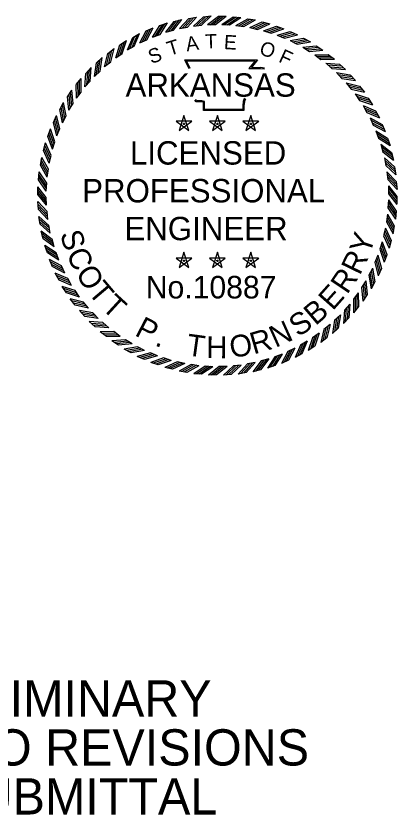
# Model space of a CAD drawing. Extents: x 172 to 3385, y 73 to 2074.
# Drawn here: x 3035 to 3298, y 104 to 655 of the extents above; entities that cross this region are included whole.
import ezdxf

# ---------------------------------------------------------------- set-up
doc = ezdxf.new("R2010")
doc.units = 0
doc.layers.add('G-ANNO-TEXT', color=7, linetype='Continuous')
doc.layers.add('R_Border Prem', color=7, linetype='Continuous')

msp = doc.modelspace()

# ---------------------------------------------------------------- linework, layer by layer
at = {"layer": 'G-ANNO-TEXT'}
for p, q in [((3144.09, 651.46), (3149.34, 652.84)), ((3154.11, 653.5), (3159.46, 654.45)), ((3164.27, 654.72), (3169.68, 655.22)), ((3174.55, 655.02), (3179.98, 655.02)), ((3184.72, 654.61), (3190.13, 654.22)), ((3194.86, 653.3), (3200.22, 652.45)), ((3204.86, 651.15), (3210.14, 649.86)), ((3124.72, 644.92), (3129.67, 647.14)), ((3134.27, 648.59), (3139.39, 650.4)), ((3138.4, 643.99), (3143.66, 645.37)), ((3147.82, 646.53), (3153.18, 647.47)), ((3157.43, 648.29), (3162.84, 648.79)), ((3167.14, 649.25), (3172.58, 649.25)), ((3176.91, 649.4), (3182.33, 649)), ((3186.65, 648.74), (3192.02, 647.9)), ((3196.3, 647.29), (3201.59, 646)), ((3214.65, 648.18), (3219.8, 646.46)), ((3115.51, 640.47), (3120.25, 643.1)), ((3129.21, 640.67), (3134.34, 642.49)), ((3205.8, 645.04), (3210.96, 643.32)), ((3215.09, 642.01), (3220.09, 639.87)), ((3224.17, 644.41), (3229.16, 642.27)), ((3233.33, 639.87), (3238.13, 637.33)), ((3106.69, 635.28), (3111.21, 638.29)), ((3111.82, 631.83), (3116.58, 634.46)), ((3120.33, 636.61), (3125.29, 638.84)), ((3224.09, 638.23), (3228.89, 635.68)), ((3242.1, 634.59), (3246.67, 631.66)), ((3098.33, 629.38), (3102.59, 632.75)), ((3103.73, 626.36), (3108.26, 629.38)), ((3232.74, 633.72), (3237.33, 630.78)), ((3250.39, 628.6), (3254.71, 625.31)), ((3090.49, 622.8), (3094.45, 626.52)), ((3096.12, 620.25), (3100.38, 623.63)), ((3241, 628.5), (3245.32, 625.2)), ((3083.22, 615.61), (3086.86, 619.63)), ((3248.8, 622.63), (3252.83, 618.98)), ((3258.17, 621.95), (3262.19, 618.31)), ((3076.57, 607.83), (3079.86, 612.15)), ((3089.04, 613.52), (3093.01, 617.24)), ((3256.08, 616.13), (3259.8, 612.16)), ((3265.36, 614.68), (3269.08, 610.72)), ((3082.54, 606.24), (3086.19, 610.27)), ((3262.81, 609.05), (3266.19, 604.79)), ((3271.94, 606.84), (3275.31, 602.58)), ((3070.58, 599.54), (3073.51, 604.11)), ((3076.66, 598.44), (3079.97, 602.76)), ((3268.92, 601.44), (3271.94, 596.91)), ((3065.3, 590.77), (3067.84, 595.57)), ((3277.84, 598.48), (3280.85, 593.96)), ((3071.45, 590.18), (3074.39, 594.77)), ((3274.39, 593.35), (3277.02, 588.59)), ((3060.76, 581.61), (3062.89, 586.6)), ((3066.94, 581.53), (3069.48, 586.33)), ((3150.83, 586.54), (3147.44, 576.12)), ((3154.22, 576.13), (3150.84, 586.55)), ((3173.85, 586.54), (3170.46, 576.12)), ((3177.24, 576.13), (3173.86, 586.55)), ((3196.88, 586.54), (3193.48, 576.12)), ((3200.26, 576.13), (3196.88, 586.55)), ((3279.17, 584.84), (3281.4, 579.87)), ((3283.03, 589.66), (3285.66, 584.91)), ((3156.31, 582.56), (3145.35, 582.57)), ((3145.36, 582.56), (3154.22, 576.12)), ((3147.45, 576.13), (3156.32, 582.56)), ((3150.05, 580.81), (3151.68, 580.81)), ((3150.84, 581.4), (3150.84, 580.02)), ((3179.33, 582.56), (3168.37, 582.57)), ((3168.38, 582.56), (3177.24, 576.12)), ((3170.47, 576.13), (3179.34, 582.56)), ((3173.07, 580.81), (3174.7, 580.81)), ((3173.86, 581.4), (3173.86, 580.02)), ((3202.35, 582.56), (3191.39, 582.57)), ((3191.4, 582.56), (3200.26, 576.12)), ((3193.49, 576.13), (3202.36, 582.56)), ((3196.1, 580.81), (3197.72, 580.81)), ((3196.89, 581.4), (3196.89, 580.02)), ((3287.48, 580.45), (3289.7, 575.5)), ((3056.99, 572.09), (3058.71, 577.24)), ((3063.16, 572.53), (3065.3, 577.53)), ((3283.23, 575.96), (3285.05, 570.83)), ((3060.13, 563.24), (3061.85, 568.4)), ((3291.15, 570.9), (3292.96, 565.78)), ((3054.02, 562.3), (3055.31, 567.58)), ((3286.55, 566.77), (3287.93, 561.51)), ((3051.87, 552.3), (3052.72, 557.66)), ((3057.88, 553.74), (3059.17, 559.03)), ((3289.09, 557.35), (3290.03, 551.99)), ((3294.02, 561.08), (3295.4, 555.83)), ((3050.56, 542.16), (3050.95, 547.57)), ((3056.43, 544.09), (3057.27, 549.46)), ((3290.85, 547.74), (3291.35, 542.33)), ((3296.06, 551.06), (3297.01, 545.71)), ((3297.28, 540.9), (3297.78, 535.49)), ((3050.08, 531.94), (3050.03, 537.36)), ((3055.77, 534.35), (3056.17, 539.77)), ((3291.8, 538.03), (3291.86, 532.59)), ((3055.92, 524.58), (3055.87, 530.02)), ((3297.65, 530.67), (3297.7, 525.25)), ((3050.45, 521.71), (3049.95, 527.12)), ((3291.96, 528.26), (3291.56, 522.84)), ((3056.88, 514.87), (3056.38, 520.28)), ((3291.3, 518.52), (3290.46, 513.15)), ((3297.17, 520.45), (3296.77, 515.04)), ((3051.66, 511.55), (3050.72, 516.9)), ((3058.64, 505.26), (3057.69, 510.62)), ((3289.85, 508.87), (3288.56, 503.58)), ((3295.86, 510.31), (3295.01, 504.95)), ((3053.71, 501.53), (3052.33, 506.78)), ((3056.58, 491.71), (3054.77, 496.83)), ((3061.18, 495.84), (3059.8, 501.1)), ((3287.6, 499.37), (3285.88, 494.21)), ((3293.71, 500.3), (3292.42, 495.03)), ((3064.5, 486.65), (3062.68, 491.78)), ((3150.83, 492.15), (3147.44, 481.73)), ((3154.22, 481.74), (3150.84, 492.16)), ((3173.85, 492.15), (3170.46, 481.73)), ((3177.24, 481.74), (3173.86, 492.16)), ((3196.88, 492.15), (3193.48, 481.73)), ((3200.26, 481.74), (3196.88, 492.16)), ((3060.25, 482.16), (3058.03, 487.11)), ((3156.31, 488.17), (3145.35, 488.18)), ((3145.36, 488.17), (3154.22, 481.72)), ((3147.45, 481.74), (3156.32, 488.17)), ((3150.05, 486.42), (3151.68, 486.42)), ((3150.84, 487.01), (3150.84, 485.63)), ((3179.33, 488.17), (3168.37, 488.18)), ((3168.38, 488.17), (3177.24, 481.72)), ((3170.47, 481.74), (3179.34, 488.17)), ((3173.07, 486.42), (3174.7, 486.42)), ((3173.86, 487.01), (3173.86, 485.63)), ((3202.35, 488.17), (3191.39, 488.18)), ((3191.4, 488.17), (3200.26, 481.72)), ((3193.49, 481.74), (3202.36, 488.17)), ((3196.1, 486.42), (3197.72, 486.42)), ((3196.89, 487.01), (3196.89, 485.63)), ((3284.57, 490.08), (3282.43, 485.08)), ((3290.74, 490.51), (3289.02, 485.37)), ((3068.56, 477.77), (3066.33, 482.73)), ((3280.79, 481.08), (3278.24, 476.27)), ((3286.97, 481), (3284.83, 476.01)), ((3064.7, 472.95), (3062.07, 477.69)), ((3073.34, 469.26), (3070.7, 474.02)), ((3276.28, 472.42), (3273.34, 467.84)), ((3282.43, 471.83), (3279.89, 467.04)), ((3069.89, 464.13), (3066.88, 468.65)), ((3078.8, 461.17), (3075.79, 465.7)), ((3271.06, 464.17), (3267.76, 459.84)), ((3075.79, 455.77), (3072.42, 460.03)), ((3084.92, 453.56), (3081.54, 457.82)), ((3277.15, 463.07), (3274.22, 458.5)), ((3265.19, 456.37), (3261.54, 452.33)), ((3271.16, 454.78), (3267.87, 450.46)), ((3082.37, 447.93), (3078.65, 451.89)), ((3091.65, 446.48), (3087.92, 450.45)), ((3258.69, 449.09), (3254.72, 445.36)), ((3264.51, 447), (3260.87, 442.98)), ((3089.56, 440.66), (3085.54, 444.3)), ((3098.93, 439.98), (3094.89, 443.63)), ((3251.61, 442.36), (3247.35, 438.98)), ((3097.34, 434.01), (3093.02, 437.3)), ((3106.73, 434.1), (3102.4, 437.41)), ((3244, 436.24), (3239.47, 433.23)), ((3257.24, 439.81), (3253.28, 436.09)), ((3105.63, 428.02), (3101.06, 430.95)), ((3114.98, 428.89), (3110.4, 431.83)), ((3235.91, 430.78), (3231.15, 428.14)), ((3249.4, 433.23), (3245.14, 429.86)), ((3114.39, 422.74), (3109.6, 425.28)), ((3123.64, 424.38), (3118.83, 426.92)), ((3227.4, 426), (3222.43, 423.77)), ((3241.04, 427.33), (3236.52, 424.32)), ((3123.56, 418.2), (3118.57, 420.33)), ((3132.64, 420.6), (3127.64, 422.74)), ((3141.93, 417.57), (3136.77, 419.29)), ((3218.52, 421.94), (3213.39, 420.12)), ((3232.22, 422.14), (3227.47, 419.51)), ((3133.07, 414.43), (3127.93, 416.15)), ((3151.43, 415.32), (3146.14, 416.61)), ((3161.08, 413.87), (3155.71, 414.71)), ((3170.82, 413.21), (3165.4, 413.61)), ((3190.3, 414.32), (3184.89, 413.82)), ((3199.91, 416.08), (3194.55, 415.13)), ((3209.33, 418.62), (3204.07, 417.24)), ((3213.46, 414.02), (3208.34, 412.21)), ((3223.01, 417.69), (3218.06, 415.47)), ((3142.86, 411.46), (3137.59, 412.75)), ((3152.87, 409.31), (3147.51, 410.16)), ((3163.01, 408), (3157.6, 408.39)), ((3180.59, 413.36), (3175.15, 413.31)), ((3193.62, 409.1), (3188.27, 408.16)), ((3203.64, 411.15), (3198.39, 409.77)), ((3173.23, 407.52), (3167.81, 407.47)), ((3183.46, 407.89), (3178.05, 407.39))]:
    msp.add_line(p, q, dxfattribs=at)
for points in [[(3138.39, 643.98), (3144.08, 651.45)], [(3140.08, 644.41), (3145.78, 651.88)], [(3141.9, 644.93), (3147.59, 652.4)], [(3143.65, 645.37), (3149.34, 652.84)], [(3147.82, 646.52), (3154.11, 653.5)], [(3149.54, 646.81), (3155.83, 653.79)], [(3151.39, 647.18), (3157.68, 654.15)], [(3153.17, 647.48), (3159.46, 654.45)], [(3157.42, 648.28), (3164.26, 654.71)], [(3159.16, 648.43), (3166.01, 654.86)], [(3161.04, 648.64), (3167.88, 655.07)], [(3162.84, 648.79), (3169.68, 655.22)], [(3167.14, 649.24), (3174.54, 655.02)], [(3168.88, 649.22), (3176.29, 655)], [(3170.77, 649.27), (3178.17, 655.04)], [(3172.58, 649.25), (3179.98, 655.02)], [(3176.9, 649.39), (3184.71, 654.61)], [(3178.64, 649.25), (3186.45, 654.46)], [(3180.52, 649.15), (3188.33, 654.37)], [(3182.32, 649), (3190.13, 654.22)], [(3186.64, 648.74), (3194.85, 653.29)], [(3188.36, 648.45), (3196.58, 653)], [(3190.23, 648.2), (3198.45, 652.75)], [(3192.02, 647.9), (3200.23, 652.46)], [(3196.29, 647.28), (3204.86, 651.14)], [(3197.99, 646.85), (3206.55, 650.71)], [(3121.93, 637.31), (3126.31, 645.61)], [(3123.63, 638.12), (3128.02, 646.42)], [(3125.29, 638.84), (3129.67, 647.15)], [(3129.21, 640.67), (3134.26, 648.58)], [(3130.86, 641.23), (3135.92, 649.15)], [(3132.62, 641.9), (3137.68, 649.81)], [(3134.33, 642.49), (3139.39, 650.4)], [(3199.83, 646.45), (3208.39, 650.31)], [(3201.58, 646), (3210.14, 649.86)], [(3205.79, 645.03), (3214.65, 648.17)], [(3207.45, 644.47), (3216.3, 647.61)], [(3209.25, 643.91), (3218.1, 647.05)], [(3210.96, 643.32), (3219.81, 646.46)], [(3111.82, 631.82), (3115.5, 640.46)], [(3113.35, 632.65), (3117.04, 641.29)], [(3114.98, 633.6), (3118.67, 642.24)], [(3116.57, 634.46), (3120.26, 643.1)], [(3120.33, 636.6), (3124.71, 644.91)], [(3215.08, 642.01), (3224.16, 644.41)], [(3216.68, 641.31), (3225.76, 643.71)], [(3218.43, 640.6), (3227.51, 643)], [(3220.08, 639.88), (3229.16, 642.28)], [(3224.08, 638.23), (3233.33, 639.87)], [(3103.73, 626.36), (3106.69, 635.27)], [(3105.19, 627.31), (3108.15, 636.22)], [(3106.74, 628.39), (3109.69, 637.3)], [(3108.25, 629.38), (3111.21, 638.29)], [(3225.61, 637.4), (3234.86, 639.04)], [(3227.3, 636.55), (3236.55, 638.19)], [(3228.89, 635.69), (3238.14, 637.33)], [(3232.74, 633.72), (3242.09, 634.59)], [(3096.12, 620.24), (3098.33, 629.37)], [(3097.5, 621.31), (3099.71, 630.44)], [(3098.95, 622.52), (3101.16, 631.64)], [(3100.37, 623.63), (3102.59, 632.75)], [(3234.2, 632.76), (3243.55, 633.63)], [(3235.81, 631.78), (3245.16, 632.65)], [(3237.32, 630.79), (3246.67, 631.66)], [(3240.99, 628.5), (3250.38, 628.6)], [(3090.32, 614.7), (3091.78, 623.98)], [(3091.67, 616.02), (3093.12, 625.3)], [(3093, 617.24), (3094.45, 626.52)], [(3154.33, 618.7), (3151.44, 624.96), (3201.49, 624.99), (3197.31, 619.74), (3200.71, 619.78), (3203.55, 619.82), (3206.39, 619.51)], [(3155.05, 619.03), (3152.67, 624.17), (3199.85, 624.2), (3195.65, 618.92), (3200.72, 618.99), (3203.51, 619.02), (3206.3, 618.72)], [(3242.37, 627.43), (3251.76, 627.53)], [(3243.89, 626.32), (3253.29, 626.42)], [(3245.32, 625.21), (3254.71, 625.31)], [(3084.96, 608.94), (3085.64, 618.31)], [(3086.18, 610.27), (3086.86, 619.64)], [(3089.04, 613.52), (3090.49, 622.79)], [(3248.79, 622.63), (3258.16, 621.95)], [(3250.08, 621.45), (3259.44, 620.77)], [(3251.5, 620.21), (3260.87, 619.53)], [(3252.83, 618.99), (3262.2, 618.31)], [(3079.96, 602.76), (3079.86, 612.15)], [(3082.54, 606.23), (3083.22, 615.6)], [(3083.72, 607.52), (3084.4, 616.88)], [(3256.08, 616.13), (3265.35, 614.68)], [(3257.26, 614.84), (3266.54, 613.39)], [(3258.58, 613.5), (3267.86, 612.05)], [(3259.8, 612.17), (3269.08, 610.72)], [(3076.66, 598.43), (3076.57, 607.82)], [(3077.74, 599.81), (3077.64, 609.2)], [(3078.85, 601.33), (3078.75, 610.73)], [(3262.8, 609.05), (3271.93, 606.84)], [(3263.87, 607.67), (3273, 605.46)], [(3073.39, 593.25), (3072.52, 602.6)], [(3074.38, 594.76), (3073.51, 604.11)], [(3265.08, 606.22), (3274.2, 604.01)], [(3266.19, 604.79), (3275.31, 602.58)], [(3268.92, 601.44), (3277.83, 598.48)], [(3069.48, 586.33), (3067.84, 595.58)], [(3071.45, 590.18), (3070.58, 599.53)], [(3072.41, 591.64), (3071.54, 600.99)], [(3193.6, 597.72), (3192.75, 597.02), (3192.47, 595.99), (3192.18, 593.39), (3192.18, 589.93), (3164.24, 589.93), (3164.24, 594.6), (3164.24, 595.64), (3163.11, 595.99), (3159.13, 595.99), (3158.43, 597.06)], [(3193.1, 598.33), (3192.05, 597.48), (3191.69, 596.13), (3191.39, 593.43), (3191.39, 590.72), (3165.03, 590.72), (3165.03, 594.6), (3165.03, 596.23), (3163.23, 596.78), (3159.56, 596.78), (3159.09, 597.5)], [(3269.87, 599.98), (3278.78, 597.02)], [(3270.95, 598.43), (3279.86, 595.47)], [(3271.94, 596.92), (3280.85, 593.96)], [(3066.94, 581.52), (3065.3, 590.77)], [(3067.77, 583.05), (3066.13, 592.3)], [(3068.62, 584.74), (3066.98, 593.99)], [(3274.38, 593.35), (3283.02, 589.67)], [(3275.21, 591.82), (3283.85, 588.13)], [(3276.16, 590.19), (3284.8, 586.5)], [(3064.56, 575.87), (3062.17, 584.95)], [(3065.29, 577.52), (3062.89, 586.6)], [(3277.02, 588.6), (3285.66, 584.91)], [(3279.16, 584.84), (3287.47, 580.45)], [(3063.16, 572.52), (3060.76, 581.6)], [(3063.86, 574.12), (3061.46, 583.2)], [(3279.87, 583.24), (3288.17, 578.85)], [(3280.68, 581.54), (3288.98, 577.15)], [(3281.4, 579.88), (3289.71, 575.5)], [(3060.7, 564.89), (3057.56, 573.74)], [(3061.26, 566.69), (3058.12, 575.54)], [(3061.85, 568.4), (3058.71, 577.25)], [(3283.23, 575.96), (3291.14, 570.91)], [(3283.79, 574.31), (3291.71, 569.25)], [(3060.13, 563.23), (3056.99, 572.09)], [(3284.46, 572.55), (3292.37, 567.49)], [(3285.05, 570.84), (3292.96, 565.78)], [(3058.32, 555.43), (3054.46, 563.99)], [(3058.72, 557.27), (3054.86, 565.83)], [(3059.16, 559.02), (3055.3, 567.58)], [(3286.54, 566.78), (3294.01, 561.09)], [(3286.97, 565.08), (3294.44, 559.39)], [(3287.49, 563.27), (3294.96, 557.58)], [(3057.27, 549.46), (3052.71, 557.67)], [(3057.89, 553.73), (3054.03, 562.3)], [(3287.93, 561.52), (3295.4, 555.83)], [(3289.08, 557.35), (3296.06, 551.06)], [(3056.43, 544.08), (3051.88, 552.29)], [(3056.72, 545.8), (3052.16, 554.02)], [(3056.97, 547.67), (3052.42, 555.89)], [(3289.37, 555.63), (3296.35, 549.34)], [(3289.74, 553.78), (3296.71, 547.49)], [(3290.04, 552), (3297.01, 545.71)], [(3056.17, 539.76), (3050.95, 547.57)], [(3290.84, 547.75), (3297.27, 540.9)], [(3290.99, 546.01), (3297.42, 539.16)], [(3055.78, 534.34), (3050.56, 542.15)], [(3055.92, 536.08), (3050.7, 543.89)], [(3056.02, 537.96), (3050.8, 545.77)], [(3291.2, 544.13), (3297.63, 537.29)], [(3291.35, 542.33), (3297.78, 535.49)], [(3055.87, 530.02), (3050.03, 537.37)], [(3055.87, 528.21), (3050.03, 535.56)], [(3291.8, 538.03), (3297.64, 530.68)], [(3291.8, 536.29), (3297.64, 528.93)], [(3055.93, 526.32), (3050.09, 533.68)], [(3055.93, 524.58), (3050.09, 531.93)], [(3291.86, 534.4), (3297.7, 527.05)], [(3291.86, 532.59), (3297.7, 525.24)], [(3056.38, 520.28), (3049.95, 527.12)], [(3056.53, 518.48), (3050.1, 525.32)], [(3291.71, 524.65), (3296.93, 516.84)], [(3291.81, 526.53), (3297.02, 518.72)], [(3291.95, 528.27), (3297.17, 520.46)], [(3056.74, 516.6), (3050.31, 523.45)], [(3056.89, 514.86), (3050.46, 521.7)], [(3291.3, 518.53), (3295.85, 510.32)], [(3291.56, 522.84), (3296.78, 515.03)], [(3057.69, 510.61), (3050.72, 516.9)], [(3057.99, 508.83), (3051.02, 515.12)], [(3058.36, 506.98), (3051.38, 513.27)], [(3290.46, 513.15), (3295.02, 504.94)], [(3290.76, 514.94), (3295.31, 506.72)], [(3291.01, 516.81), (3295.56, 508.59)], [(3058.64, 505.26), (3051.67, 511.55)], [(3289.84, 508.88), (3293.7, 500.31)], [(3059.8, 501.09), (3052.33, 506.78)], [(3060.24, 499.34), (3052.77, 505.03)], [(3060.76, 497.52), (3053.29, 503.22)], [(3288.56, 503.59), (3292.42, 495.03)], [(3289.01, 505.34), (3292.87, 496.78)], [(3289.41, 507.18), (3293.27, 498.62)], [(3061.19, 495.83), (3053.72, 501.52)], [(3062.68, 491.77), (3054.77, 496.83)], [(3287.03, 497.72), (3290.17, 488.87)], [(3287.59, 499.37), (3290.73, 490.52)], [(3063.27, 490.06), (3055.35, 495.12)], [(3063.94, 488.3), (3056.02, 493.36)], [(3064.5, 486.65), (3056.59, 491.7)], [(3285.88, 494.21), (3289.02, 485.36)], [(3286.47, 495.92), (3289.61, 487.07)], [(3066.33, 482.73), (3058.02, 487.11)], [(3067.05, 481.07), (3058.75, 485.46)], [(3283.16, 486.74), (3285.56, 477.66)], [(3283.87, 488.49), (3286.27, 479.41)], [(3284.57, 490.09), (3286.97, 481.01)], [(3067.86, 479.37), (3059.56, 483.75)], [(3068.56, 477.77), (3060.26, 482.15)], [(3280.79, 481.09), (3282.43, 471.84)], [(3282.44, 485.09), (3284.84, 476.01)], [(3070.7, 474.01), (3062.07, 477.7)], [(3071.56, 472.42), (3062.93, 476.11)], [(3072.51, 470.79), (3063.88, 474.48)], [(3278.25, 476.28), (3279.89, 467.03)], [(3279.11, 477.87), (3280.75, 468.62)], [(3279.96, 479.55), (3281.6, 470.31)], [(3073.35, 469.26), (3064.71, 472.94)], [(3274.34, 469.36), (3275.21, 460.01)], [(3275.32, 470.97), (3276.19, 461.62)], [(3276.28, 472.43), (3277.15, 463.08)], [(3075.79, 465.69), (3066.88, 468.65)], [(3076.78, 464.18), (3067.86, 467.13)], [(3077.86, 462.63), (3068.94, 465.59)], [(3078.81, 461.17), (3069.9, 464.13)], [(3271.06, 464.18), (3271.16, 454.79)], [(3273.35, 467.85), (3274.22, 458.5)], [(3081.54, 457.81), (3072.41, 460.03)], [(3082.65, 456.39), (3073.53, 458.6)], [(3267.77, 459.85), (3267.87, 450.46)], [(3268.88, 461.27), (3268.98, 451.88)], [(3269.99, 462.8), (3270.09, 453.41)], [(3083.86, 454.94), (3074.73, 457.15)], [(3084.93, 453.56), (3075.8, 455.77)], [(3261.55, 452.34), (3260.87, 442.97)], [(3262.77, 453.67), (3262.09, 444.3)], [(3264.01, 455.09), (3263.33, 445.73)], [(3265.19, 456.38), (3264.51, 447.01)], [(3087.93, 450.44), (3078.65, 451.89)], [(3089.15, 449.11), (3079.87, 450.56)], [(3090.47, 447.76), (3081.19, 449.22)], [(3091.65, 446.48), (3082.37, 447.93)], [(3257.4, 447.91), (3255.95, 438.63)], [(3258.69, 449.09), (3257.24, 439.81)], [(3094.9, 443.62), (3085.53, 444.3)], [(3096.23, 442.4), (3086.86, 443.08)], [(3097.65, 441.16), (3088.29, 441.84)], [(3250.23, 441.3), (3248.02, 432.17)], [(3251.61, 442.37), (3249.4, 433.24)], [(3254.73, 445.37), (3253.28, 436.09)], [(3256.06, 446.59), (3254.61, 437.31)], [(3098.94, 439.98), (3089.57, 440.66)], [(3102.41, 437.4), (3093.02, 437.3)], [(3103.83, 436.29), (3094.44, 436.19)], [(3244, 436.25), (3241.04, 427.34)], [(3247.35, 438.98), (3245.14, 429.85)], [(3248.78, 440.09), (3246.57, 430.97)], [(3105.36, 435.18), (3095.97, 435.08)], [(3106.74, 434.1), (3097.35, 434.01)], [(3110.41, 431.82), (3101.06, 430.95)], [(3111.92, 430.83), (3102.57, 429.96)], [(3235.91, 430.79), (3232.23, 422.15)], [(3239.48, 433.23), (3236.52, 424.32)], [(3240.99, 434.22), (3238.03, 425.3)], [(3242.54, 435.3), (3239.58, 426.38)], [(3113.53, 429.85), (3104.18, 428.98)], [(3114.99, 428.89), (3105.64, 428.02)], [(3118.84, 426.92), (3109.59, 425.28)], [(3120.43, 426.06), (3111.18, 424.42)], [(3122.11, 425.21), (3112.87, 423.57)], [(3225.8, 425.3), (3221.41, 417)], [(3227.4, 426), (3223.01, 417.7)], [(3231.16, 428.14), (3227.47, 419.51)], [(3232.75, 429.01), (3229.06, 420.37)], [(3234.38, 429.95), (3230.69, 421.32)], [(3123.65, 424.38), (3114.4, 422.74)], [(3127.65, 422.73), (3118.57, 420.33)], [(3129.3, 422), (3120.22, 419.61)], [(3131.05, 421.3), (3121.97, 418.9)], [(3132.65, 420.6), (3123.57, 418.2)], [(3136.77, 419.29), (3127.92, 416.15)], [(3213.4, 420.12), (3208.34, 412.21)], [(3215.11, 420.71), (3210.05, 412.79)], [(3216.87, 421.38), (3211.81, 413.46)], [(3218.52, 421.94), (3213.47, 414.03)], [(3222.44, 423.77), (3218.06, 415.46)], [(3224.1, 424.49), (3219.71, 416.19)], [(3138.48, 418.7), (3129.63, 415.56)], [(3140.28, 418.14), (3131.43, 415)], [(3141.93, 417.57), (3133.08, 414.43)], [(3146.15, 416.6), (3137.59, 412.74)], [(3147.9, 416.16), (3139.34, 412.3)], [(3149.74, 415.76), (3141.18, 411.9)], [(3151.43, 415.33), (3142.87, 411.47)], [(3155.71, 414.71), (3147.5, 410.15)], [(3157.5, 414.41), (3149.28, 409.86)], [(3159.37, 414.16), (3151.15, 409.6)], [(3161.09, 413.87), (3152.88, 409.32)], [(3165.4, 413.61), (3157.59, 408.39)], [(3184.89, 413.82), (3178.05, 407.39)], [(3186.69, 413.97), (3179.85, 407.54)], [(3188.57, 414.18), (3181.72, 407.75)], [(3190.31, 414.33), (3183.46, 407.9)], [(3194.56, 415.13), (3188.27, 408.16)], [(3196.34, 415.43), (3190.05, 408.46)], [(3198.19, 415.8), (3191.9, 408.82)], [(3199.91, 416.08), (3193.62, 409.11)], [(3204.08, 417.24), (3198.39, 409.77)], [(3205.83, 417.68), (3200.14, 410.21)], [(3207.64, 418.2), (3201.95, 410.73)], [(3209.34, 418.63), (3203.65, 411.16)], [(3167.21, 413.46), (3159.4, 408.24)], [(3169.09, 413.36), (3161.28, 408.14)], [(3170.83, 413.22), (3163.02, 408)], [(3175.15, 413.31), (3167.8, 407.47)], [(3176.96, 413.31), (3169.61, 407.47)], [(3178.85, 413.37), (3171.49, 407.53)], [(3180.59, 413.37), (3173.24, 407.53)]]:
    msp.add_lwpolyline(points, dxfattribs=at)

# ---------------------------------------------------------------- texts
for s, height, rotation, p in [('A', 9.87, 8.6788, (3152.8, 630.75)), ('T', 9.87, 1.4789, (3165.55, 632.71)), ('E', 9.87, 356.672, (3178.19, 632.41)), ('T', 9.87, 16.9015, (3140.81, 627.62)), ('O', 9.87, 341.2218, (3202.16, 629.02)), ('S', 9.87, 19.7726, (3128.26, 621.98)), ('F', 9.87, 335.3628, (3215.47, 623.82)), ('S', 15, 287.2223, (3065.15, 504.9)), ('Y', 15, 72.0481, (3278.89, 489.93)), ('C', 15, 294.5183, (3069.38, 491.24)), ('R', 15, 64.0225, (3272.09, 475.74)), ('O', 15, 302.1791, (3075.66, 477.6)), ('R', 15, 55.9969, (3263.38, 462.65)), ('T', 15, 310.2047, (3084.12, 464.34)), ('E', 15, 48.3361, (3253.43, 451.4)), ('T', 15, 317.5007, (3093.35, 453.42)), ('B', 15, 40.3105, (3241.5, 441.14)), ('P', 15, 332.4576, (3116.2, 435.14)), ('S', 15, 33.0144, (3229.51, 433.35)), ('N', 15, 24.2592, (3213.96, 426.1)), ('T', 15, 352.1568, (3152.01, 421.15)), ('O', 15, 8.208, (3183.34, 419.26)), ('R', 15, 16.2336, (3198.89, 421.61)), ('H', 15, 359.4528, (3166.18, 419.2)), ('.', 15, 340.4832, (3130.19, 427.96))]:
    msp.add_text(s, height=height, rotation=rotation, dxfattribs=at).set_placement(p)
for s, height, p in [('ARKANSAS', 16.115, (3110.52, 599.52)), ('LICENSED', 16.115, (3113.59, 552.68)), ('PROFESSIONAL', 16.1152, (3080.59, 526.59)), ('ENGINEER', 16.115, (3109.75, 500.5)), ('No.10887', 15.54, (3124.48, 460.32))]:
    msp.add_text(s, height=height, dxfattribs=at).set_placement(p)
at = {"layer": 'R_Border Prem'}
for s, p in [('PRELIMINARY', (2943.25, 171.81)), ('SUBJECT TO REVISIONS', (2837.74, 138.01)), ('90% SUBMITTAL', (2909.98, 104.2))]:
    msp.add_text(s, height=25, dxfattribs=at).set_placement(p)

doc.saveas('drawing.dxf')
